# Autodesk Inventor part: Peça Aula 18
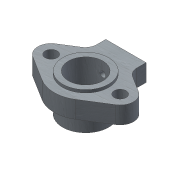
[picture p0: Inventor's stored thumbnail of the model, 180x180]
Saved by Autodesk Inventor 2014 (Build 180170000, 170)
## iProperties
Created: 2013-02
Part Number: Peça Aula 18
Material: Resina fenólica
Document SubType Name: Modeling
Designer: Daniel Severino
Density: 1 g/cm^3
Appearance: Wood - Painted White
Author: Daniel Severino
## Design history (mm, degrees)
sketch "Esboço1"
  geometry: L1 (-29.19, 46.615)-(-72.29, 19.626); L2 (0, 0)-(-137.251, 0); L3 (0, 0)-(0, 85.604); L4 (29.19, 46.615)-(72.29, 19.626); L5 (-29.19, -46.615)-(-72.29, -19.626); L6 (29.19, -46.615)-(72.29, -19.626); C1 r 30 at (0, 0); C2 r 10.5 at (60, 0); C3 r 10.5 at (-60, 0); A1 r 23.156 centre (-60, 0) between (-72.29, 19.626) and (-72.29, -19.626); A2 r 55 centre (0, 0) between (-29.19, -46.615) and (29.19, -46.615); A3 r 55 centre (0, 0) between (29.19, 46.615) and (-29.19, 46.615); A4 r 23.156 centre (60, 0) between (72.29, -19.626) and (72.29, 19.626); 1 further point
  constraints: 12 end point, 8 point on circle, 7 centre point, 6 symmetric about line, 4 coincident, 4 tangent
  dimensions: "d0" = 60 diameter of C1; "d2" = 60 distance of C3.centre L2.start; "d3" = 21 diameter of C3; "d4" = 21 diameter of C2; "d5" = 60 distance of C2.centre C1.centre
extrude "Extrusão1" new body sketch "Esboço1" distance "d7" = 30; taper "d8" = 0 deg
sketch "Esboço2"
  geometry: C1 r 30 at (0, 0) reference; C2 r 40 at (0, 0); A1 r 55 centre (0, 0) between (-29.19, -46.615) and (29.19, -46.615) reference
  constraints: 1 centre point, 1 coincident
  dimensions: "d10" = 10 radial gap between concentric circles of C1 C2
extrude "Extrusão2" join sketch "Esboço2" distance "d11" = 5; taper "d12" = 0 deg
sketch "Esboço3"
  geometry: C1 r 30 at (0, 0) reference; C2 r 40 at (0, 0) reference
extrude "Extrusão3" join sketch "Esboço3" distance "d13" = 30; taper "d14" = 0 deg
sketch "Esboço4"
  geometry: L1 (72.29, 19.626)-(29.19, 46.615) reference; L2 (-29.19, 46.615)-(-72.29, 19.626) reference; L3 (-35, 70)-(35, 70); L4 (35, 70)-(35, 42.977); L5 (-35, 42.977)-(-35, 70); C1 r 40 at (0, 0) reference; C2 r 30 at (0, 0) reference; A1 r 55 centre (0, 0) between (29.19, 46.615) and (-29.19, 46.615) reference
  constraints: 6 end point, 2 point on line, 2 vertical, 1 horizontal
  dimensions: "d15" = 70 distance of L3.start L3.end; "d17" = 35 distance from line of C1.centre L5; "d18" = 70 distance from line of L3 C2.centre
extrude "Extrusão4" join sketch "Esboço4" distance "d19" = 30; taper "d20" = 0 deg
fillet "Arredondamento1" dims "d21" = 20
sketch "Esboço5"
  geometry: L1 (70, 0)-(0, 0) reference; L2 (70, 0)-(70, 30) reference; L3 (0, 30)-(70, 30) reference; L4 (0, 0)-(0, 30) reference; L5 (65, 25)-(65, 5); L6 (65, 5)-(5, 5); L7 (5, 5)-(5, 25); L8 (5, 25)-(65, 25); 1 further point
  constraints: 8 end point, 3 other
  dimensions: "d22" = 5 distance between parallel lines of L1 L6
extrude "Extrusão5" cut sketch "Esboço5" stored distance "d23" = 30; taper "d24" = 0 deg
sketch "Esboço6"
  geometry: C1 r 5 at (35, 15); 1 further point
  constraints: 1 centre point
  dimensions: "d25" = 10 diameter of C1
extrude "Extrusão6" cut sketch "Esboço6" distance "d27" = 70; taper "d28" = 0 deg
fillet "Arredondamento3" dims "d34" = 6
node "Sólido1"
